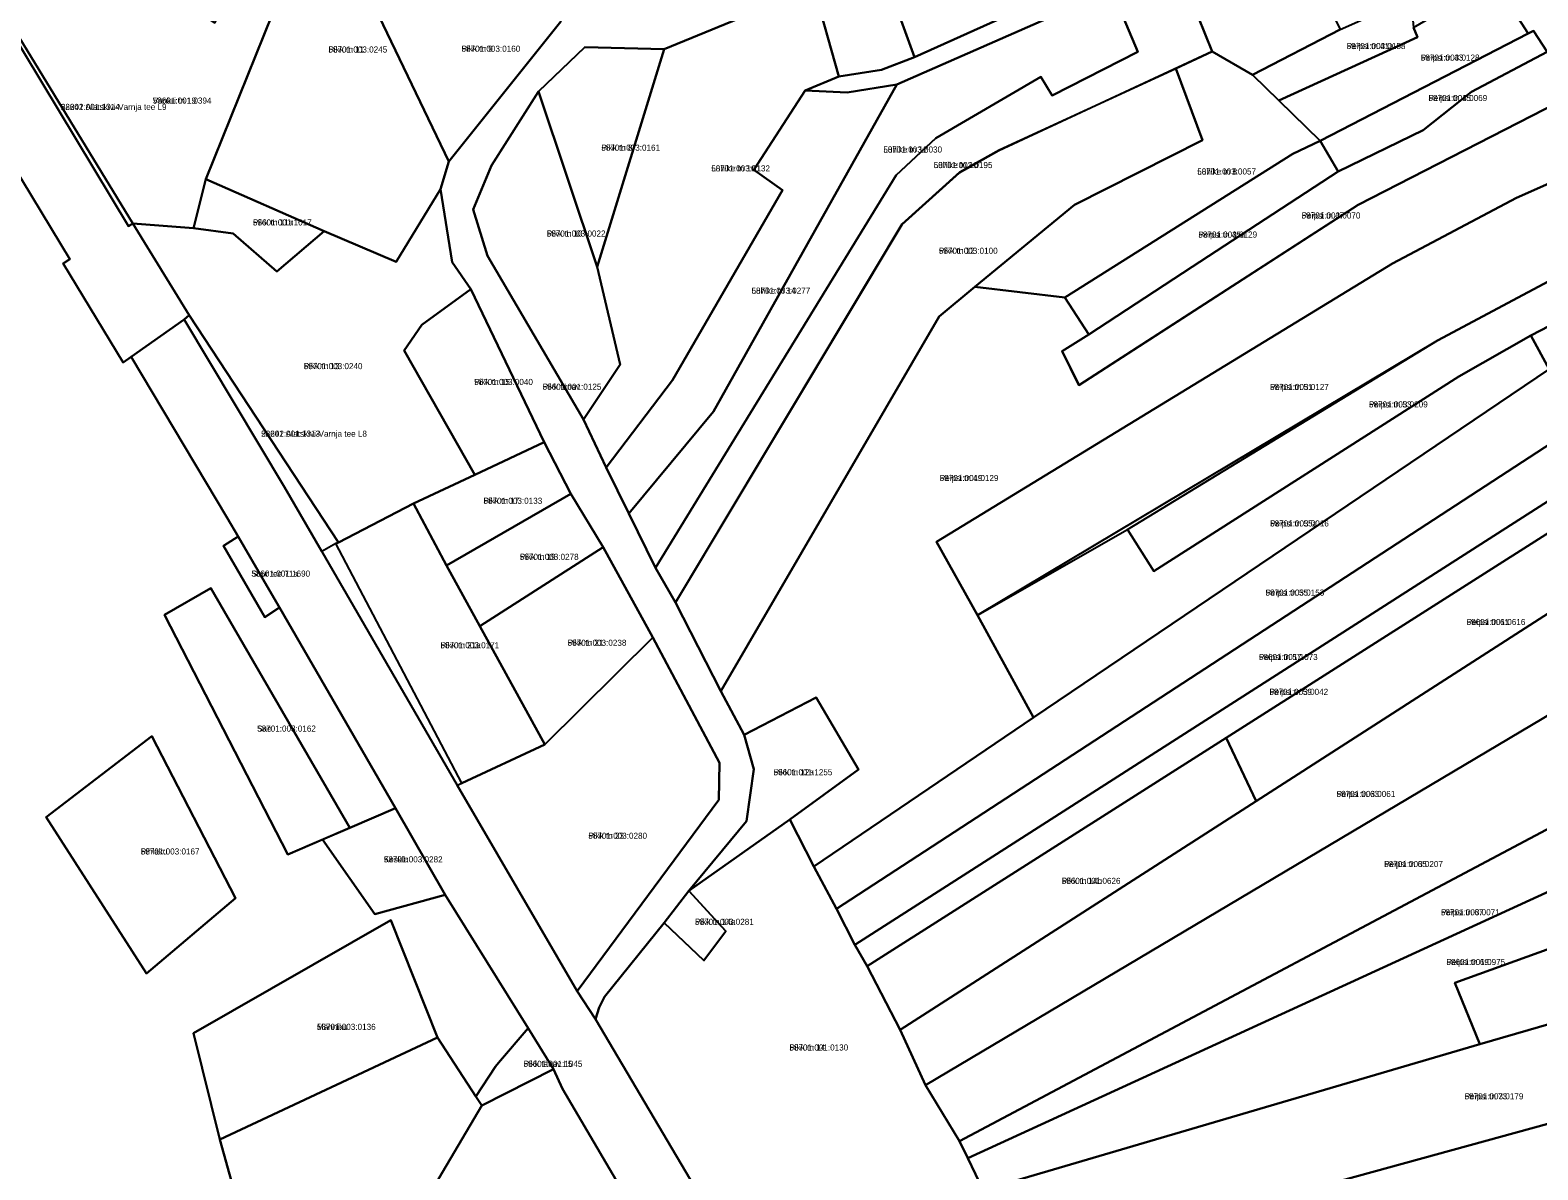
# Model space of a CAD drawing. Extents: x 663371 to 690098, y 6476568 to 6518353.
# Drawn here: x 687904.6 to 688276.7, y 6491998.7 to 6492280 of the extents above; entities that cross this region are included whole.
import ezdxf

# ---------------------------------------------------------------- set-up
doc = ezdxf.new("R2010")
doc.units = 0
for name, color, linetype in [('L_AADRESS', 7, 'Continuous'), ('PIIR', 7, 'Continuous'), ('TUNNUS', 7, 'Continuous')]:
    doc.layers.add(name, color=color, linetype=linetype)

msp = doc.modelspace()

# ---------------------------------------------------------------- linework, layer by layer
at = {"layer": 'PIIR'}
for points in [[(688278.99, 6492274.73), (688275.61, 6492279.88), (688274.32, 6492279.22), (688265.92, 6492292.28), (688256.41, 6492309.4), (688246.32, 6492321.62), (688232.41, 6492342.93), (688230, 6492346.63), (688221.38, 6492364.54), (688213.95, 6492381.34), (688209.13, 6492390.26), (688203.57, 6492400.22), (688195.24, 6492419.29), (688187.08, 6492435), (688184.54, 6492440.33), (688180.18, 6492448.35), (688174.88, 6492455.41), (688160.23, 6492479.29), (688153.21, 6492490.87), (688139.77, 6492518.16), (688125.34, 6492549.07)], [(687894.43, 6492288.82), (687928.83, 6492231.64), (687929.9, 6492232.35), (687943.83, 6492209.65), (687942.58, 6492208.66), (687929.52, 6492199.43), (687927.55, 6492198.03), (687912.73, 6492222.45), (687914.4, 6492223.54), (687895.47, 6492254.71)], [(688098.03, 6492290.61), (688061.06, 6492275.35), (688041.49, 6492275.87), (688030.03, 6492264.91), (688018.41, 6492246.6), (688013.95, 6492235.76), (688017.45, 6492224.33), (688041.18, 6492183.91), (688046.74, 6492172.12), (688052.37, 6492160.73), (688058.89, 6492147.33), (688063.83, 6492138.79), (688075.04, 6492116.9), (688080.78, 6492106.13), (688083.21, 6492097.61), (688081.4, 6492084.8), (688067.17, 6492067.59), (688061.06, 6492059.7), (688046.37, 6492041.45), (688044.99, 6492038.78), (688044.13, 6492035.89), (688039.58, 6492042.83), (688074.53, 6492090.08), (688074.75, 6492099.2), (688058.3, 6492130.1), (688046.04, 6492152.44), (688038.02, 6492165.62), (688031.48, 6492178.34), (688013.35, 6492216.11), (688008.72, 6492222.76), (688005.84, 6492240.83), (688007.94, 6492247.62), (688035.52, 6492282.19)], [(687895.47, 6492254.71), (687914.4, 6492223.54), (687912.73, 6492222.45), (687927.55, 6492198.03), (687929.52, 6492199.43), (687953.21, 6492159.7), (687955.91, 6492155.06), (687952.28, 6492152.75), (687962.49, 6492135.18), (687966.09, 6492137.53), (687994.78, 6492088.02), (687983.46, 6492083.16), (687949.15, 6492142.29), (687937.76, 6492135.7), (687968.17, 6492076.52), (687976.76, 6492080.25), (687989.68, 6492061.83), (688007, 6492066.61), (688027.46, 6492033.67), (688020.15, 6492025.17), (688019.44, 6492024.22), (688014.62, 6492016.84), (688005.15, 6492031.36), (687993.57, 6492060.32), (687944.92, 6492032.46), (687951.41, 6492006.22), (687964.9, 6491957.82)], [(688050.63, 6491993.79), (688035.95, 6492018.7), (688033.74, 6492023.55), (688027.46, 6492033.67), (688007, 6492066.61), (687994.78, 6492088.02), (687966.09, 6492137.53), (687962.43, 6492143.84), (687955.91, 6492155.06), (687953.21, 6492159.7), (687929.52, 6492199.43), (687942.58, 6492208.66), (687967.35, 6492167.21), (687976.57, 6492151.33), (688009.94, 6492093.64), (688039.58, 6492042.83), (688044.13, 6492035.89), (688084.07, 6491968.29)]]:
    msp.add_lwpolyline(points, dxfattribs=at)
for points in [[(687992.09, 6492303.09), (687986.57, 6492292.04), (688007.94, 6492247.62), (688005.84, 6492240.83), (687994.89, 6492222.84), (687977.17, 6492230.46), (687947.92, 6492243.24), (687974.65, 6492309.67), (687976.52, 6492315.01), (687997.26, 6492364.25), (688008.51, 6492363.22)], [(687895.03, 6492289.39), (687956.1, 6492345.77), (687960.6, 6492338.49), (687925.4, 6492298.08), (687950.14, 6492281.83), (687971.02, 6492318.59), (687974.65, 6492309.67), (687947.92, 6492243.24), (687944.94, 6492231.13), (687929.9, 6492232.35)], [(688232.41, 6492342.93), (688246.32, 6492321.62), (688236.81, 6492319.07), (688234.88, 6492318.24), (688224.53, 6492313.9), (688214.37, 6492308.19), (688187.68, 6492296.27), (688171.57, 6492290.01), (688118.51, 6492266.59), (688106.24, 6492264.66), (688095.83, 6492265.14), (688104.18, 6492268.6), (688114.71, 6492270.25), (688122.81, 6492273.41), (688184.51, 6492301.17), (688229.05, 6492320.45), (688238.77, 6492326.55), (688229.75, 6492341.79)], [(688175.77, 6492320.04), (688184.51, 6492301.17), (688122.81, 6492273.41), (688114.31, 6492297.03)], [(688214.37, 6492308.19), (688227.86, 6492280.21), (688206.26, 6492269.01), (688196.27, 6492274.77), (688187.68, 6492296.27)], [(687992.09, 6492303.09), (688021.07, 6492295.16), (688032.16, 6492291.13), (688035.52, 6492282.19), (688007.94, 6492247.62), (687986.57, 6492292.04)], [(688187.68, 6492296.27), (688196.27, 6492274.77), (688143.64, 6492250.23), (688133.88, 6492244.78), (688119.71, 6492231.98), (688063.83, 6492138.79), (688058.89, 6492147.33), (688118.33, 6492244.23), (688128.13, 6492253.4), (688154, 6492268.51), (688156.82, 6492263.95), (688177.94, 6492274.72), (688171.57, 6492290.01)], [(688098.03, 6492290.61), (688114.31, 6492297.03), (688122.81, 6492273.41), (688114.71, 6492270.25), (688104.18, 6492268.6)], [(688246.02, 6492280.66), (688265.92, 6492292.28), (688274.32, 6492279.22), (688222.97, 6492252.76), (688212.78, 6492262.68), (688246.98, 6492278.34)], [(687929.9, 6492232.35), (687928.83, 6492231.64), (687894.43, 6492288.82), (687895.03, 6492289.39)], [(688044.56, 6492221.61), (688061.06, 6492275.35), (688098.03, 6492290.61), (688104.18, 6492268.6), (688095.83, 6492265.14), (688083.21, 6492245.53), (688090.28, 6492240.52), (688063.09, 6492193.66), (688046.74, 6492172.12), (688041.18, 6492183.91), (688050.22, 6492197.52)], [(688052.37, 6492160.73), (688073.22, 6492185.93), (688118.51, 6492266.59), (688171.57, 6492290.01), (688177.94, 6492274.72), (688156.82, 6492263.95), (688154, 6492268.51), (688128.13, 6492253.4), (688118.33, 6492244.23), (688058.89, 6492147.33)], [(688212.78, 6492262.68), (688206.26, 6492269.01), (688227.86, 6492280.21), (688245.33, 6492288.06), (688246.02, 6492280.66), (688246.98, 6492278.34)], [(688222.97, 6492252.76), (688274.32, 6492279.22), (688275.61, 6492279.88), (688278.99, 6492274.73), (688260.29, 6492264.82), (688248.37, 6492255.32), (688227.37, 6492245.19)], [(688061.06, 6492275.35), (688044.56, 6492221.61), (688030.03, 6492264.91), (688041.49, 6492275.87)], [(688187.35, 6492270.61), (688196.27, 6492274.77), (688206.26, 6492269.01), (688212.78, 6492262.68), (688222.97, 6492252.76), (688216.25, 6492249.53), (688159.92, 6492214.06), (688137.71, 6492216.66), (688162.34, 6492236.94), (688193.88, 6492252.9)], [(688278.99, 6492274.73), (688280.04, 6492273.23), (688283.42, 6492266.72), (688285.01, 6492263.89), (688232.35, 6492236.9), (688163.43, 6492192.38), (688159.32, 6492200.83), (688165.83, 6492204.91), (688191.39, 6492221.63), (688227.37, 6492245.19), (688248.37, 6492255.32), (688260.29, 6492264.82)], [(688143.77, 6492250.47), (688187.35, 6492270.61), (688193.88, 6492252.9), (688162.34, 6492236.94), (688137.71, 6492216.66), (688128.92, 6492209.4), (688075.04, 6492116.9), (688063.83, 6492138.79), (688119.82, 6492232.25), (688134.01, 6492245.03)], [(688095.83, 6492265.14), (688106.24, 6492264.66), (688118.51, 6492266.59), (688073.22, 6492185.93), (688052.37, 6492160.73), (688046.74, 6492172.12), (688063.09, 6492193.66), (688090.28, 6492240.52), (688083.21, 6492245.53)], [(688030.03, 6492264.91), (688044.56, 6492221.61), (688050.22, 6492197.52), (688041.18, 6492183.91), (688017.45, 6492224.33), (688013.95, 6492235.76), (688018.41, 6492246.6)], [(688232.35, 6492236.9), (688285.01, 6492263.89), (688288.38, 6492254.77), (688290.4, 6492247.15), (688289.73, 6492246.8), (688271.38, 6492238.62), (688240.82, 6492222.45), (688128.31, 6492153.71), (688138.42, 6492135.64), (688152.24, 6492110.4), (688097.96, 6492073.59), (688092.05, 6492085.16), (688108.98, 6492097.5), (688098.59, 6492115.3), (688080.78, 6492106.13), (688075.04, 6492116.9), (688128.92, 6492209.4), (688137.71, 6492216.66), (688159.92, 6492214.06), (688165.83, 6492204.91), (688159.32, 6492200.83), (688163.45, 6492192.38)], [(688216.25, 6492249.53), (688222.97, 6492252.76), (688227.37, 6492245.19), (688191.39, 6492221.63), (688165.83, 6492204.91), (688159.92, 6492214.06)], [(688296.65, 6492227.32), (688251.94, 6492203.45), (688138.42, 6492135.64), (688128.31, 6492153.71), (688240.82, 6492222.45), (688271.38, 6492238.62), (688289.73, 6492246.8)], [(687999.2, 6492163.2), (687980.65, 6492153.6), (687943.83, 6492209.65), (687929.9, 6492232.35), (687944.94, 6492231.13), (687954.73, 6492229.84), (687965.49, 6492220.43), (687977.17, 6492230.46), (687994.89, 6492222.84), (688005.84, 6492240.83), (688008.72, 6492222.76), (688013.35, 6492216.11), (688001.29, 6492207.32), (687996.86, 6492201), (688014.32, 6492170.25)], [(687977.17, 6492230.46), (687965.49, 6492220.43), (687954.73, 6492229.84), (687944.94, 6492231.13), (687947.92, 6492243.24)], [(688300.18, 6492217.77), (688274.97, 6492204.66), (688257.17, 6492194.56), (688181.93, 6492146.5), (688175.44, 6492156.81), (688251.94, 6492203.45), (688296.65, 6492227.32)], [(688305.6, 6492194.83), (688283.75, 6492180.57), (688103.56, 6492063.15), (688097.96, 6492073.59), (688152.24, 6492110.4), (688279.48, 6492196.35), (688274.97, 6492204.66), (688300.18, 6492217.77)], [(688031.48, 6492178.34), (688014.32, 6492170.25), (687996.86, 6492201), (688001.29, 6492207.32), (688013.35, 6492216.11)], [(687942.58, 6492208.66), (687943.83, 6492209.65), (687980.65, 6492153.6), (687980.06, 6492153.29), (687976.57, 6492151.33), (687967.35, 6492167.21)], [(688175.44, 6492156.81), (688181.93, 6492146.5), (688257.17, 6492194.56), (688274.97, 6492204.66), (688279.48, 6492196.35), (688152.24, 6492110.4), (688138.42, 6492135.64)], [(688308.98, 6492182.9), (688108.15, 6492054.29), (688103.56, 6492063.15), (688283.75, 6492180.57), (688305.6, 6492194.83)], [(688308.98, 6492182.9), (688311.88, 6492176.66), (688199.72, 6492105.36), (688111.12, 6492049.03), (688108.15, 6492054.29)], [(688038.02, 6492165.62), (688007.36, 6492147.89), (687999.2, 6492163.2), (688014.32, 6492170.25), (688031.48, 6492178.34)], [(688199.72, 6492105.36), (688311.88, 6492176.66), (688319.46, 6492161.94), (688312.72, 6492157.82), (688306.04, 6492153.36), (688207.14, 6492089.73)], [(688046.04, 6492152.44), (688015.55, 6492132.96), (688007.36, 6492147.89), (688038.02, 6492165.62)], [(687980.06, 6492153.29), (687980.65, 6492153.6), (687999.2, 6492163.2), (688007.36, 6492147.89), (688015.55, 6492132.96), (688031.63, 6492103.7), (688011.11, 6492094.19)], [(688125.56, 6492019.58), (688119.27, 6492033.24), (688207.14, 6492089.73), (688306.04, 6492153.36), (688312.72, 6492157.82), (688319.46, 6492161.94), (688330.66, 6492141.13), (688305.68, 6492126.69)], [(687955.91, 6492155.06), (687962.43, 6492143.84), (687966.09, 6492137.53), (687962.49, 6492135.18), (687952.28, 6492152.75)], [(688058.3, 6492130.1), (688031.63, 6492103.7), (688015.55, 6492132.96), (688046.04, 6492152.44)], [(687949.15, 6492142.29), (687983.46, 6492083.16), (687968.17, 6492076.52), (687937.76, 6492135.7)], [(688334.07, 6492136.27), (688335.03, 6492134.47), (688342.59, 6492121.53), (688298.87, 6492093.38), (688133.97, 6492005.77), (688125.56, 6492019.58), (688305.68, 6492126.69), (688330.66, 6492141.13)], [(688031.63, 6492103.7), (688058.3, 6492130.1), (688074.75, 6492099.2), (688074.53, 6492090.08), (688039.58, 6492042.83), (688009.94, 6492093.64), (688011.11, 6492094.19)], [(688349.16, 6492104.83), (688332.88, 6492096.92), (688302.8, 6492078.21), (688136.04, 6492001.59), (688133.97, 6492005.77), (688298.87, 6492093.38), (688327.57, 6492111.61), (688342.59, 6492121.53)], [(688092.05, 6492085.16), (688067.17, 6492067.59), (688081.4, 6492084.8), (688083.21, 6492097.61), (688080.78, 6492106.13), (688098.59, 6492115.3), (688108.98, 6492097.5)], [(687908.51, 6492085.76), (687934.61, 6492105.77), (687955.27, 6492065.8), (687933.32, 6492047.21)], [(687933.32, 6492047.21), (687955.27, 6492065.8), (687934.61, 6492105.77), (687908.51, 6492085.76)], [(688111.12, 6492049.03), (688199.72, 6492105.36), (688207.14, 6492089.73), (688119.27, 6492033.24)], [(688139.82, 6491993.72), (688136.04, 6492001.59), (688302.8, 6492078.21), (688332.88, 6492096.92), (688349.16, 6492104.83), (688355.27, 6492093.52), (688310.4, 6492064.44), (688256.22, 6492044.88), (688262.39, 6492029.73)], [(688310.4, 6492064.44), (688355.27, 6492093.52), (688362.96, 6492071.5), (688365.86, 6492057.68), (688317.72, 6492045.76), (688262.39, 6492029.73), (688256.22, 6492044.88)], [(687994.78, 6492088.02), (688007, 6492066.61), (687989.68, 6492061.83), (687976.76, 6492080.25), (687983.46, 6492083.16)], [(688076.29, 6492057.6), (688067.17, 6492067.59), (688092.05, 6492085.16), (688097.96, 6492073.59), (688103.56, 6492063.15), (688108.15, 6492054.29), (688111.12, 6492049.03), (688119.27, 6492033.24), (688125.56, 6492019.58), (688133.97, 6492005.77), (688136.04, 6492001.59), (688139.82, 6491993.72), (688133.95, 6491986.81), (688084.07, 6491968.29), (688044.13, 6492035.89), (688044.99, 6492038.78), (688046.37, 6492041.45), (688061.06, 6492059.7), (688070.81, 6492050.4)], [(688061.06, 6492059.7), (688067.17, 6492067.59), (688076.29, 6492057.6), (688070.81, 6492050.4)], [(687944.92, 6492032.46), (687993.57, 6492060.32), (688005.15, 6492031.36), (687951.41, 6492006.22)], [(688317.72, 6492045.76), (688365.86, 6492057.68), (688368.93, 6492032.78), (688330.08, 6492024.06), (688149.73, 6491974.56), (688145.02, 6491984.27), (688139.82, 6491993.72), (688262.39, 6492029.73)], [(688033.74, 6492023.55), (688016.07, 6492014.61), (688014.62, 6492016.84), (688019.44, 6492024.22), (688020.15, 6492025.17), (688027.46, 6492033.67)], [(688330.08, 6492024.06), (688368.93, 6492032.78), (688372.02, 6492011.87), (688335.39, 6492004.59), (688329.14, 6492003.97), (688159.99, 6491955.73), (688154.88, 6491965.36), (688149.73, 6491974.56)], [(688016.07, 6492014.61), (687988.05, 6491967.03), (687964.9, 6491957.82), (687951.41, 6492006.22), (688005.15, 6492031.36), (688014.62, 6492016.84)], [(688033.74, 6492023.55), (688035.95, 6492018.7), (688050.63, 6491993.79), (688067, 6491965.75), (688079.87, 6491944.07), (688088.33, 6491929.62), (688084.92, 6491928.82), (687994.44, 6491907.51), (687988.05, 6491967.03), (688016.07, 6492014.61)]]:
    msp.add_lwpolyline(points, close=True, dxfattribs=at)

# ---------------------------------------------------------------- texts
at = {"layer": 'L_AADRESS'}
for s, p in [('Pikk tn 11', (687978.21, 6492274.52)), ('Pikk tn 9', (688011.05, 6492274.71)), ('Peipsi tn 41a', (688229.51, 6492275.37)), ('Peipsi tn 43', (688247.79, 6492272.52)), ('Vankri tn 19', (687934.84, 6492261.91)), ('Peipsi tn 45', (688249.68, 6492262.54)), ('22242 Alatskivi-Varnja tee L9', (687912.16, 6492260.35)), ('Pikk tn 8', (688045.55, 6492250.29)), ('Lühike tn 12', (688115.15, 6492249.83)), ('Lühike tn 10', (688127.58, 6492245.99)), ('Lühike tn 16', (688072.68, 6492245.17)), ('Lühike tn 8', (688192.62, 6492244.41)), ('Pikk tn 11a', (687959.57, 6492231.83)), ('Peipsi tn 47', (688218.39, 6492233.55)), ('Pikk tn 10', (688032.09, 6492229.09)), ('Peipsi tn 45a', (688192.89, 6492228.84)), ('Pikk tn 12', (688128.86, 6492224.84)), ('Lühike tn 14', (688082.62, 6492215)), ('Pikk tn 13', (687972.11, 6492196.36)), ('Pikk tn 15', (688014.17, 6492192.46)), ('Pikk tänav', (688031.07, 6492191.26)), ('Peipsi tn 51', (688210.59, 6492191.22)), ('Peipsi tn 53', (688235, 6492186.91)), ('22242 Alatskivi-Varnja tee L8', (687961.61, 6492179.69)), ('Peipsi tn 49', (688129.07, 6492168.74)), ('Pikk tn 17', (688016.47, 6492163.12)), ('Peipsi tn 55a', (688210.6, 6492157.53)), ('Pikk tn 19', (688025.45, 6492149.29)), ('Suur tee 71a', (687959.19, 6492145.15)), ('Peipsi tn 55', (688209.47, 6492140.46)), ('Peipsi tn 61', (688259.1, 6492133.2)), ('Pikk tn 21a', (688005.85, 6492127.47)), ('Pikk tn 21', (688037.24, 6492128.07)), ('Peipsi tn 57', (688207.84, 6492124.56)), ('Peipsi tn 59', (688210.43, 6492115.96)), ('Sae', (687960.61, 6492106.89)), ('Pikk tn 12a', (688088.07, 6492096.12)), ('Peipsi tn 63', (688227, 6492090.76)), ('Pikk tn 23', (688042.34, 6492080.44)), ('Pihlaku', (687931.89, 6492076.56)), ('Keskla', (687991.88, 6492074.61)), ('Peipsi tn 65', (688238.75, 6492073.45)), ('Pikk tn 14b', (688159.18, 6492069.3)), ('Peipsi tn 67', (688252.77, 6492061.56)), ('Pikk tn 14a', (688068.68, 6492059.19)), ('Peipsi tn 69', (688254.11, 6492049.27)), ('Männiku', (687975.36, 6492033.27)), ('Pikk tn 14', (688091.98, 6492028.17)), ('Pikk tänav L5', (688026.38, 6492024.14)), ('Peipsi tn 73', (688258.61, 6492016.12))]:
    msp.add_text(s, height=1.5, dxfattribs=at).set_placement(p)
at = {"layer": 'TUNNUS'}
for s, p in [('58701:003:0245', (687978.21, 6492274.52)), ('58701:003:0160', (688011.05, 6492274.71)), ('58701:003:0158', (688229.51, 6492275.37)), ('58701:003:0128', (688247.79, 6492272.52)), ('58601:001:0394', (687934.84, 6492261.91)), ('58701:003:0069', (688249.68, 6492262.54)), ('58601:001:1314', (687912.16, 6492260.35)), ('58701:003:0161', (688045.55, 6492250.29)), ('58701:003:0030', (688115.15, 6492249.83)), ('58701:003:0195', (688127.58, 6492245.99)), ('58701:003:0132', (688072.68, 6492245.17)), ('58701:003:0057', (688192.62, 6492244.41)), ('58601:001:1017', (687959.57, 6492231.83)), ('58701:003:0070', (688218.39, 6492233.55)), ('58701:003:0022', (688032.09, 6492229.09)), ('58701:003:0129', (688192.89, 6492228.84)), ('58701:003:0100', (688128.86, 6492224.84)), ('58701:003:0277', (688082.62, 6492215)), ('58701:003:0240', (687972.11, 6492196.36)), ('58701:003:0040', (688014.17, 6492192.46)), ('58601:001:0125', (688031.07, 6492191.26)), ('58701:003:0127', (688210.59, 6492191.22)), ('58701:003:0209', (688235, 6492186.91)), ('58601:001:1313', (687961.61, 6492179.69)), ('58701:001:0129', (688129.07, 6492168.74)), ('58701:003:0133', (688016.47, 6492163.12)), ('58701:003:0016', (688210.6, 6492157.53)), ('58701:003:0278', (688025.45, 6492149.29)), ('58601:001:1690', (687959.19, 6492145.15)), ('58701:003:0153', (688209.47, 6492140.46)), ('58601:001:0616', (688259.1, 6492133.2)), ('58701:003:0171', (688005.85, 6492127.47)), ('58701:003:0238', (688037.24, 6492128.07)), ('58601:001:1073', (688207.84, 6492124.56)), ('58701:003:0042', (688210.43, 6492115.96)), ('58701:003:0162', (687960.61, 6492106.89)), ('58601:001:1255', (688088.07, 6492096.12)), ('58701:003:0061', (688227, 6492090.76)), ('58701:003:0280', (688042.34, 6492080.44)), ('58701:003:0167', (687931.89, 6492076.56)), ('58701:003:0282', (687991.88, 6492074.61)), ('58701:003:0207', (688238.75, 6492073.45)), ('58601:001:0626', (688159.18, 6492069.3)), ('58701:003:0071', (688252.77, 6492061.56)), ('58701:003:0281', (688068.68, 6492059.19)), ('58601:001:0975', (688254.11, 6492049.27)), ('58701:003:0136', (687975.36, 6492033.27)), ('58701:001:0130', (688091.98, 6492028.17)), ('58601:001:1045', (688026.38, 6492024.14)), ('58701:003:0179', (688258.61, 6492016.12))]:
    msp.add_text(s, height=1.5, dxfattribs=at).set_placement(p)

doc.saveas('drawing.dxf')
